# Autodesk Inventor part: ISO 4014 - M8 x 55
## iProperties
Comments: To add or edit properties for Autodesk Inventor files, use iProperties.
Created: 2004-08
Part Number: ISO 4014 - M8 x 55
Vendor: Autodesk Inc.
Document SubType Name: Modeling
Designer: John Blackburn
Material: Default
Description: Hex-Head Bolt
Standard: ISO 4014
Alert: To add or edit properties for Autodesk Inventor files, use iProperties.
Control State: 0
Master: False
Checked Out: False
Shininess: 64.0
Length Units: 11269
Angle Units: 11279
Time Units: 11290
Mass Units: 11283
Length Display Precision: 3
Angle Display Precision: 2
Compacted: True
EGR: 1
Density: 0.0
Volumn: 0.0
Area: 0.0
PropertySet Name: Model Information
Author: John Blackburn
Revision Number: 8
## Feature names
1. Body [Revolution]
2. Head [Extrusion]
3. Chamfer1 [Revolution]
4. Chamfer2
